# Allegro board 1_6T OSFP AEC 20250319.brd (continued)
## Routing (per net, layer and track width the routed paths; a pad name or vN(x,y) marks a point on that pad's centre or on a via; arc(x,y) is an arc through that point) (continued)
VCC_3V3: length 56
  TOP w0.127: v5(2.22,31.83) C914.1
  TOP w0.14: v2(0.65,37.34) 0.65,37.34 0.77,37.34
  TOP w0.178: U17.11 1.4,37.14 1.2,37.34 0.77,37.34 ; 2.23,31.83 1.93,32.14 U46.12 2.28,32.36 U46.1
  L9_SIG2 w0.254: 2.9,41.84 v6(2.91,41.84)
  L10_GND w0.203: 18.36,34.23 18.36,34.24 17.52,34.24 16.56,35.19 v6(16.56,35.65) ; 18.36,34.23 18.76,34.63 18.76,37.78 18.87,37.9 v6(18.87,38.61) ; 18.36,34.23 18.36,33.19 v6(18.61,32.94)
  L11_GND w0.254: v6(12.33,14.28) 12.84,13.77 v6(13.2,13.77)
  BOTTOM w0.203: 9.4,39.57 9.4,40.53 9.17,40.76 R32.2 R40.2 8.4,41.27 C45.1 7.57,41.29 U22.A1 ; U10.2 2.55,42.19 v6(2.91,41.84) C424.1 2.66,41.55 2.48,41.37 2.48,39.97 2.29,39.78 R580.1 2.02,39.22 2.02,39.22 ; U48.2 8.92,43.31 C909.1 8.23,43.34 8.23,43.34
  BOTTOM w0.254: 8.44,45.52 8.44,43.96 8.23,43.75 8.23,42.29 8.48,42.04 9.47,42.04 10.45,41.05 10.45,39.53 ; 8.44,45.52 8.81,45.88 15.48,45.88 15.94,45.42 15.94,44.89 16.23,44.6 R622.1 16.69,45.06 16.94,45.31 17.46,45.31 17.7,45.08 R23.2 ; 8.44,45.52 8.43,45.5 6.52,45.5 C420.1 U38.12 6.5,44.57 U38.1 ; R579.1 3.28,39.9 2.6,39.22 1.51,39.22 0.65,38.36 v2(0.65,37.34) ; 16.56,35.88 16.24,35.88 16.24,35.88 13.61,35.88 13.38,36.1 12.52,36.1 11.91,36.71 11.91,37.71 11.69,37.92 ; 16.56,35.88 v6(16.56,35.65) ; 16.56,35.88 16.56,36.05 R13.1 ; U24.4 7.31,38.81 7.31,38.82 ; R29.1 8.16,38.91 8.16,38.91
  vias: v2(9.58,14.77) v2(9.57,14.44) v2(9.56,14.03) v2(9.94,14.79) v2(9.94,14.41) v2(9.94,14.03) v2(10.32,14.79) v2(10.32,14.41) v2(10.32,14.03) v2(10.7,14.79) v2(10.7,14.41) v2(10.7,14.03) v2(11,14.65) v2(11.04,14.31) v6(1.38,34.87) v6(1.38,34.58) v6(1.38,34.28) v6(1.4,26.29) v6(1.4,25.86) v6(1.41,24.97) v6(1.41,24.51) v6(1.67,34.88) v6(1.66,34.59) v6(1.66,34.29) v6(1.77,26.29) v6(1.77,25.86) v6(1.77,24.97) v6(1.77,24.51) v7(0.64,17.04) v7(0.64,16.68) v7(0.64,16.33) v7(0.64,15.97) v7(0.64,15.62) v7(1,17.04) v7(1,16.68) v7(1,16.33) v7(1,15.97) v7(1,15.62) v7(1.38,34.87) v7(1.38,34.58) v7(1.38,34.28) v7(1.4,26.29) v7(1.4,25.86) v7(1.41,24.97) v7(1.41,24.51) v7(1.67,34.88) v7(1.66,34.59) v7(1.66,34.29) v7(1.77,26.29) v7(1.77,25.86) v7(1.77,24.97) v7(1.77,24.51) v8(1.38,34.87) v8(1.38,34.58) v8(1.38,34.28) v8(1.4,26.29) v8(1.4,25.86) v8(1.41,24.97) v8(1.41,24.51) v8(1.67,34.88) v8(1.66,34.59) v8(1.66,34.29) v8(1.77,26.29) v8(1.77,25.86) v8(1.77,24.97) v8(1.77,24.51) v10(0.64,17.04) v10(0.64,16.68) v10(0.64,16.33) v10(0.64,15.97) v10(0.64,15.62) v10(1,17.04) v10(1,16.68) v10(1,16.33) v10(1,15.97) v10(1,15.62) v11(0.64,17.04) v11(0.64,16.68) v11(0.64,16.33) v11(0.64,15.97) v11(0.64,15.62) v11(1,17.04) v11(1,16.68) v11(1,16.33) v11(1,15.97) v11(1,15.62)
VCC_3V3_DMM: length 5.3
  L11_GND w0.071: v6(18.2,43.93) 18.52,43.62 18.52,42.44 18.16,42.09 17.5,42.09 16.22,40.81 v6(16.22,40.8)
  BOTTOM w0.14: R23.1 R24.1 18.2,43.93 v6(18.2,43.93)
VCC_OSFP: length 43.2
  L7_PWR2 w0.076: v7(19.89,43.66) 19.89,43.12 18.52,41.75 18.52,40.41 18.02,39.91 18.02,38.77 17.67,38.42 17.67,37.87 17.98,37.56 17.98,34 19,32.98 19,29.94 18.01,28.95 18.01,19.32 17.37,18.67 17.37,12.58 16.85,12.07 10.95,12.07 v2(10.94,12.08)
  L10_GND w0.081: v7(19.89,43.66) 19.9,43.66 v6(19.9,43.92)
  BOTTOM w0.14: C939.2 12.5,12.37 12.35,12.22 11.2,12.22 U32.1 ; R600.2 19.76,44.6 19.9,44.46 v6(19.9,43.92)
  vias: v1(10.81,2.92) v1(10.81,2.61) v1(10.81,2.31) v1(10.81,2) v1(10.81,1.7) v1(10.81,1.39) v2(9.58,12.08) v2(9.91,11.62) v2(9.91,11.21) v2(9.91,10.81) v2(9.91,10.4) v2(9.91,9.99) v2(9.92,9.17) v2(9.92,8.16) v2(9.92,7.14) v2(9.92,6) v2(9.92,4.98) v2(9.99,4.3) v2(9.99,3.89) v2(10.04,12.07) v2(10.04,3.46) v2(10.2,2.92) v2(10.2,2.61) v2(10.2,2.31) v2(10.2,2) v2(10.2,1.7) v2(10.2,1.39) v2(10.32,11.62) v2(10.32,11.21) v2(10.32,10.81) v2(10.32,10.4) v2(10.32,9.99) v2(10.27,3.21) v2(10.4,4.3) v2(10.4,3.89) v2(10.4,3.48) v2(10.5,2.92) v2(10.5,2.61) v2(10.5,2.31) v2(10.5,2) v2(10.5,1.7) v2(10.5,1.39) v2(10.55,12.04) v2(10.55,8.79) v2(10.55,7.9) v2(10.55,6.76) v2(10.55,5.62) v2(10.55,4.6) v2(10.72,11.62) v2(10.72,11.21) v2(10.72,10.81) v2(10.72,10.4) v2(10.72,9.99) v2(10.81,4.3) v2(10.81,3.89) v2(10.81,3.48) v6(9.89,2.92) v6(9.89,2.61) v6(9.89,2.31) v6(9.89,2) v6(9.89,1.7) v6(9.89,1.39)
VDD_0P6: length 37
  TOP w0.132: U1.E15 v2(5.91,29.61)
  L2_GND w0.127: v4(1.94,21.01) 1.26,20.32 1.26,15.85 3.75,13.36 5.9,13.36 v1(6.3,12.97) ; v2(6.98,27.61) 6.98,27.11 6.34,26.48 v4(5.35,26.48)
  L3_GND w0.254: v4(17.85,37.75) 17.85,36.65 17.6,36.4 17.6,36.05 17.59,36.04 17.59,33.42 17.94,33.06 17.94,30.38 17.69,30.13 17.33,30.13 16.82,29.61 v2(15.48,29.61)
  L4_SIG1 w0.127: v4(1.94,21.01) 2.15,21.21 2.15,22.13 3.14,23.12 3.14,25.02 3.62,25.51 4.76,25.51 5.35,26.09 v4(5.35,26.48)
  L4_SIG1 w0.203: v9(18.18,40.88) 18.18,39.61 17.72,39.15 17.72,37.88 v4(17.85,37.75)
  L9_SIG2 w0.074: v9(18.18,40.88) 18.18,40.88
  L9_SIG2 w0.203: 18.18,40.88 17.94,40.88 17.74,40.67 17.05,40.67 v6(16.83,40.45)
  vias: v1(2.55,21.59) v1(2.93,21.59) v1(3.31,21.26) v1(3.93,21.14) v1(4.28,20.41) v1(4.28,19.9) v1(4.45,21.15) v1(4.79,20.42) v1(4.79,19.92) v1(4.95,21.15) v1(5.3,20.42) v1(5.3,19.92) v1(5.46,21.15) v1(5.81,20.42) v1(5.81,19.92) v1(5.97,21.15) v1(6.31,20.42) v1(6.31,19.92) v1(6.48,21.15) v1(6.82,20.42) v1(6.82,19.92) v1(7.33,20.42) v1(7.33,19.92) v1(7.84,20.42) v1(7.84,19.92) v1(7.87,19.36) v1(7.87,18.85) v1(8.35,20.42) v1(8.35,19.92) v1(8.37,19.36) v1(8.37,18.85) v1(9.11,20.34) v1(9.66,20.36) v2(2.48,21.26) v2(2.48,20.86) v2(2.48,20.45) v2(2.48,20.04) v2(2.48,19.64) v2(2.88,21.26) v2(2.88,20.86) v2(2.88,20.45) v2(2.88,20.04) v2(2.88,19.64) v2(3.31,20.86) v2(3.29,20.45) v2(3.29,20.04) v2(3.29,19.64) v2(3.69,20.45) v2(3.69,20.04) v2(3.69,19.64) v2(5.48,29.11) v2(6.48,28.11) v2(6.98,28.61) v2(7.48,29.11) v2(7.98,29.61) v2(8.48,28.11) v2(8.98,28.61) v2(8.98,27.61) v2(9.48,29.11) v2(9.98,29.61) v2(10.98,29.11) v2(11.48,29.61) v2(11.98,28.11) v2(12.48,28.61) v2(12.48,27.61) v2(12.98,29.11) v2(13.48,29.61) v2(13.98,28.11) v2(14.48,28.61) v2(14.48,27.61) v2(15.04,29.11) v3(2.55,21.59) v3(2.93,21.59) v3(3.31,21.26) v4(2.55,21.59) v4(2.93,21.59) v4(3.31,21.26) v9(2.55,21.59) v9(2.93,21.59) v9(3.31,21.26)
VDD_0P6_EN: length 44.7
  TOP w0.14: v1(8.74,12.65) R635.1 8.35,12.65 R607.1
  L2_GND w0.071: v3(18.3,10.92) 18.3,11.12 17.4,12.02 14.73,12.02 14.1,12.65 v1(8.74,12.65)
  L3_GND w0.081: v3(18.3,10.92) 17.8,11.42 17.8,14.56 18.65,15.41 18.65,17.93 20.03,19.31 20.03,26.97 19.32,27.67 19.32,35.41 19.11,35.62 19.11,37.23 19.54,37.66 v9(19.54,38.01)
  L9_SIG2 w0.074: v9(19.54,38.01) 19.49,37.97 19.49,37.97 19.42,37.9 17.94,37.9 16.98,38.87 16.98,39.16 arc(16.92,39.36) 16.77,39.51 arc(16.69,39.54) 16.6,39.55 arc(16.52,39.54) 16.45,39.51 16.32,39.46 arc(16.3,39.46) 16.27,39.46 16.18,39.46 arc(16.12,39.46) 16.07,39.49 v6(15.92,39.57)
VDD_0P6_PG: length 7.7
  TOP w0.14: R620.2 3.03,12.12 v1(3.58,12.12) 3.85,12.12 4.27,12.53 U20.21
  L2_GND w0.071: v8(2.63,11.23) 2.63,11.55 3.19,12.12 v1(3.58,12.12)
  L11_GND w0.071: v6(5.77,12.22) 5.54,11.99 5.21,11.99 5.2,11.99 3.13,11.99 2.91,11.76 2.91,11.51 v8(2.63,11.23)
  BOTTOM w0.14: v6(5.77,12.22) U21.21
VDD_0P94: length 22.4
  L2_GND w0.127: v4(18.53,19.66) 18.77,19.42 19.26,19.42 19.71,18.97 19.71,15.87 17.89,14.05 17.87,14.05 16.87,13.05 v1(16.87,12.99)
  L7_PWR2 w0.254: v8(18.75,40.24) 18.96,40.03 18.96,36.8 19.69,36.07 19.69,34.78 19.28,34.37 19.28,29.17 19.57,28.88 19.54,28.86
  L11_GND w0.254: v8(18.75,40.24) 18.45,40.24 17.54,41.15 v6(17.46,41.15)
  BOTTOM w0.203: U2.T10 v6(17.46,41.15)
  vias: v1(12.11,20.39) v1(12.11,19.88) v1(12.62,20.39) v1(12.62,19.88) v1(13.12,20.39) v1(13.12,19.88) v1(13.68,20.37) v1(13.68,19.86) v1(14.19,20.37) v1(14.19,19.86) v1(14.66,20.95) v1(14.7,20.37) v1(14.7,19.86) v1(15.16,20.95) v1(15.21,20.37) v1(15.21,19.86) v1(15.67,20.95) v1(15.72,20.37) v1(15.72,19.86) v1(16.18,20.95) v1(16.22,20.37) v1(16.22,19.86) v1(16.69,20.95) v1(16.73,20.37) v1(16.73,19.86) v1(17.2,20.95) v1(17.24,20.37) v1(17.24,19.86) v1(17.77,21.24) v1(17.77,20.96) v1(17.77,20.68) v1(17.77,20.4) v1(17.77,20.12) v1(18.05,21.24) v1(18.05,20.96) v1(18.05,20.68) v1(18.05,20.4) v1(18.05,20.12) v1(19.09,23.42) v1(19.09,23.14) v1(19.09,22.86) v1(19.39,23.43) v1(19.39,23.15) v1(19.39,22.87) v1(19.66,23.43) v1(19.66,23.15) v1(19.66,22.87) v2(10.45,20.65) v2(10.45,20.3) v2(10.45,19.97) v2(10.81,20.3) v2(10.83,19.97) v3(17.77,21.24) v3(17.77,20.96) v3(17.77,20.68) v3(17.77,20.4) v3(17.77,20.12) v3(18.05,21.24) v3(18.05,20.96) v3(18.05,20.68) v3(18.05,20.4) v3(18.05,20.12) v3(19.09,23.42) v3(19.09,23.14) v3(19.09,22.86) v3(19.39,23.43) v3(19.39,23.15) v3(19.39,22.87) v3(19.66,23.43) v3(19.66,23.15) v3(19.66,22.87) v4(17.77,21.24) v4(17.77,20.96) v4(17.77,20.68) v4(17.77,20.4) v4(17.77,20.12) v4(18.05,21.24) v4(18.05,20.96) v4(18.05,20.68) v4(18.05,20.4) v4(18.05,20.12) v4(19.09,23.42) v4(19.09,23.14) v4(19.09,22.86) v4(19.39,23.43) v4(19.39,23.15) v4(19.39,22.87) v4(19.66,23.43) v4(19.66,23.15) v4(19.66,22.87) v6(18.77,28.84) v6(18.77,28.54) v6(18.77,28.23) v6(19.08,28.85) v6(19.08,28.54) v6(19.08,28.24) v6(19.41,28.85) v6(19.41,28.54) v6(19.41,28.24) v7(18.77,28.84) v7(18.77,28.54) v7(18.77,28.23) v7(19.08,28.85) v7(19.08,28.54) v7(19.08,28.24) v7(19.12,21.28) v7(19.12,20.95) v7(19.12,20.62) v7(19.12,20.29) v7(19.12,19.96) v7(19.41,28.85) v7(19.41,28.54) v7(19.41,28.24) v7(19.37,21.11) v7(19.37,20.78) v7(19.37,20.45) v7(19.37,20.12) v7(19.37,19.79) v8(18.77,28.84) v8(18.77,28.54) v8(18.77,28.23) v8(19.08,28.85) v8(19.08,28.54) v8(19.08,28.24) v8(19.41,28.85) v8(19.41,28.54) v8(19.41,28.24) v9(18.77,28.84) v9(18.77,28.54) v9(18.77,28.23) v9(19.08,28.85) v9(19.08,28.54) v9(19.08,28.24) v9(19.12,21.28) v9(19.12,20.95) v9(19.12,20.62) v9(19.12,20.29) v9(19.12,19.96) v9(19.41,28.85) v9(19.41,28.54) v9(19.41,28.24) v9(19.37,21.11) v9(19.37,20.78) v9(19.37,20.45) v9(19.37,20.12) v9(19.37,19.79)
VDD_0P94_EN: length 34.5
  TOP w0.14: R715.1 v3(18.12,12.13) 18.01,12.13 R710.1
  L3_GND w0.081: v8(19.41,37.01) 19.41,35.75 19.58,35.57 19.58,27.75 20.25,27.08 20.25,19.12 18.89,17.76 18.89,15.36 17.99,14.46 17.99,12.26 v3(18.12,12.13)
  L11_GND w0.071: v8(19.41,37.01) 18.38,37.01 17.77,37.62 16.42,37.62 16.3,37.5 14.36,37.5 v6(13.8,38.05)
  BOTTOM w0.14: v6(13.8,38.05) 13.8,38.5 13.8,38.51 13.81,38.52 14.51,39.22 U2.E1
VDD_0P94_PG: length 2.3
  TOP w0.14: U26.21 14.68,12.44 14.53,12.29 13.1,12.29 R621.2
VDD_1P2: length 28.3
  L10_GND w0.081: v6(16.52,39.92) 16.77,40.06 17.33,40.06 17.54,39.86 18.67,39.86 19.19,39.34 19.19,38.64 20.23,37.6 20.23,17.98 v6(19.65,17.4)
  BOTTOM w0.14: 13.47,17.42 U37.A3
  BOTTOM w0.178: 18.12,17.76 19.29,17.76 v6(19.65,17.4)
VDD_1P2_EN: length 42.5
  L9_SIG2 w0.074: v6(19.22,10.97) 19.22,11.8 17.91,13.1 17.91,16.73 20.17,18.99 20.17,29.35 19.24,30.28 19.24,34.46 19.72,34.93 19.72,37.25 19.45,37.52 v8(19.24,37.52)
  L11_GND w0.071: v6(14.18,38.08) 14.18,38.03 14.54,37.67 16.16,37.67 16.29,37.8 18.45,37.8 18.73,37.52 v8(19.24,37.52)
  BOTTOM w0.14: v6(14.18,38.08) 14.18,38.51 14.55,38.87 U2.C1 ; v6(19.22,10.97) 19.22,11.68 18.01,12.89 R850.1 14.47,12.89 14.17,13.2 R852.1
VDD_1P2_PG: length 0.6
  BOTTOM w0.14: U37.A2 13.85,16.45 R756.1
VDD_1P8: length 87.9
  TOP w0.127: 1.41,32 v1(1.42,32.01) ; C915.1 1.41,32
  TOP w0.178: 1.41,32 U46.11
  TOP w0.203: R22.1 18.99,33.33 19.35,32.97 19.35,30.65 19.35,30.64 19.35,30.15 19.02,29.82 R693.2 19.38,29.4 v1(19.38,29.29) ; U1.AD12 v2(15.48,28.36) U1.AD13 ; R854.2 19.37,29.27 v1(19.38,29.29) ; v2(5.48,28.61) v2(5.48,28.11) ; v1(19.38,29.29) 19.88,29.29 v3(19.93,29.34) ; v1(19.38,29.29) v1(18.3,29.29) ; R769.1 R819.1 R818.1 R694.2 1.74,26.8 R691.2 0.89,26.8 0.69,26.6 R75.2 ; C426.1 1.29,35.44 v1(1.39,35.54) 1.4,35.55 U17.1
  TOP w0.254: v1(18.98,25.99) 18.98,25.98 R690.2 ; R694.2 1.77,26.6 1.97,26.4 2.57,26.4 2.7,26.53 v9(2.7,26.53)
  L2_GND w0.203: v2(15.48,28.36) 16.4,29.29 v1(18.3,29.29) ; v1(1.42,32.01) 2.09,32.68 2.09,33.9 1.83,34.15 1.83,34.74 1.73,34.85 1.73,35.2 v1(1.39,35.54) 2.41,35.54 2.5,35.44 v9(2.84,35.44) 2.82,35.42 v1(2.82,34.77) ; v1(19.38,29.29) 19.38,26.39 v1(18.98,25.99)
  L3_GND w0.254: v9(19.93,33.47) v3(19.93,29.34)
  L4_SIG1 w0.203: v4(2.11,23.14) 1.97,23.28 1.97,24.6 v2(5.48,28.11)
  L6_PWR1 w0.254: v9(18.81,42.94) 18.54,42.67 17.71,42.67 17.52,42.86 v9(3.67,42.86)
  L9_SIG2 w0.254: v9(18.81,42.94) v6(18.81,42.44) 18.81,42.18 20.06,40.93 20.06,33.6 v9(19.93,33.47) ; v9(2.7,26.53) 3.21,27.04 3.21,28.85
  L11_GND w0.203: v6(11,43.4) 11,43.77 10.4,44.38 8.01,44.38 7.45,43.81 7.09,43.81 6.67,44.22 5.71,44.22 5.11,43.63 v6(4.08,43.63) 3.84,43.63 v8(3.67,43.46)
  L11_GND w0.254: v6(6.63,35.13) 3.21,35.13 2.92,35.42 2.92,35.9 v6(2.66,36.17)
  BOTTOM w0.203: C83.2 2.66,36.87 v6(2.66,36.17) U8.A2 ; R583.1 R855.1 R856.1 ; R856.1 4.08,44.32 4.61,44.85 C421.1 5,45.04 U38.11 ; R856.1 3.4,44.17 3.11,43.88 C425.2 2.55,43.67 U10.6 ; C932.2 6.33,35.13 v6(6.63,35.13) U47.A2 ; U48.6 10.91,43.31 v6(11,43.4)
  BOTTOM w0.254: R841.2 18.79,42.46 v6(18.81,42.44)
VDD_3P3: length 1
  TOP w0.254: U1.D5 v2(5.48,24.86) U1.D6 ; U1.AD5 v2(15.48,24.66) U1.AD6
  vias: v6(2.88,24.84) v6(2.88,24.56) v6(3.17,24.84) v6(3.17,24.56) v7(2.88,24.84) v7(2.88,24.56) v7(3.17,24.84) v7(3.17,24.56) v8(2.88,24.84) v8(2.88,24.56) v8(3.17,24.84) v8(3.17,24.56)
VDD_3P3_ESD0:
  vias: v2(5.48,25.61)
VDD_3P3_ESD1:
  vias: v2(15.48,25.61)
VDDEFUSE_0P94: length 1.2
  L9_SIG2 w0.254: v7(10.7,28.71) 10.48,28.48 v2(10.48,27.61)
  BOTTOM w0.14: C940.1 arc(10.45,30.11) v2(10.48,30.11)
  vias: v6(17.35,22.99) v8(17.35,22.99)
VDDIO_1P8_EN: length 18.7
  L11_GND w0.071: v6(1.71,37.04) 1.84,37.16 2.25,37.16 2.37,37.04 2.88,37.04 3.47,37.63 4.72,37.63 6.04,38.94 13.96,38.94 14.89,38.02 15.95,38.02 16.22,38.29 v6(16.22,39.05)
  BOTTOM w0.14: v6(1.71,37.04) 1.71,35.85 R602.1 1.72,35.62 1.92,35.41 U8.B1
VIN1: length 5.2
  TOP w0.178: R629.1 R618.1 7.75,14.73 v1(7.76,14.74)
  TOP w0.203: 2.55,13.99 2.55,15.04 ; 2.55,13.99 2.41,13.84 R620.1 ; 2.55,13.99 2.57,14 U20.18
  vias: v1(1.92,16.09) v1(1.92,15.79) v1(2.22,16.09) v1(2.22,15.79) v1(2.22,15.48) v1(2.53,16.09) v1(2.53,15.79) v1(2.53,15.48) v1(2.83,16.09) v1(2.83,15.79) v1(2.83,15.48) v1(3.17,15.45) v1(7.07,15.4) v1(7.07,15.07) v1(7.05,14.74) v1(7.4,15.4) v1(7.4,15.07) v1(7.4,14.74) v1(7.76,15.4) v1(7.76,15.07) v1(8.14,15.4) v1(8.14,15.07) v1(8.14,14.74)
VIN2: length 2.7
  TOP w0.14: 12.9,14.57 R621.1 ; U26.18 13.5,14 13.3,14.2 13.3,14.48
  vias: v1(12.39,15.4) v1(12.39,15.09) v1(12.39,14.79) v1(12.7,15.4) v1(12.7,15.09) v1(12.7,14.79) v1(13,15.4) v1(13,15.09) v1(13,14.79) v1(13.31,15.4) v1(13.31,15.09) v1(13.31,14.79) v1(17.63,15.72) v1(17.64,15.43) v1(17.63,15.14) v1(17.95,16.03) v1(17.94,15.74) v1(17.94,15.44) v1(17.94,15.14) v1(18.27,16.03) v1(18.27,15.73) v1(18.28,15.44) v1(18.57,16.02) v1(18.57,15.72)
VIN3: length 2.8
  L11_GND w0.203: v6(14.17,15.37) v6(13.82,15.37) v6(13.47,15.37) 12.89,15.37 v6(12.89,15.37)
  BOTTOM w0.196: v6(13.47,15.37) v6(13.82,15.37)
  BOTTOM w0.203: v6(14.17,15.37) v6(13.82,15.37) ; C648.1 12.7,15.37 v6(13.47,15.37)
VIN4: length 3.4
  L11_GND w0.203: v6(2.34,14.91) 2.46,14.78 2.46,12.71 v6(1.65,11.9)
  vias: v6(1.96,15.72) v6(1.96,15.44) v6(1.96,15.16) v6(2.24,15.72) v6(2.24,15.44) v6(2.24,15.16) v6(2.52,15.72) v6(2.52,15.44) v6(2.52,15.16) v6(2.8,15.72) v6(2.8,15.44) v6(2.8,15.16) v6(7.08,15.85) v6(7.08,15.46) v6(7.08,15.08) v6(7.33,15.65) v6(7.33,15.27) v6(7.33,14.89) v6(7.68,15.65) v6(7.68,15.27) v6(7.68,14.89) v6(8.01,15.65) v6(8.01,15.27) v6(8.04,14.89)
BOOT0: length 3.5
  L10_GND w0.081: v6(16.83,39.05) 16.83,38.78 16.69,38.64 16.69,37.86 17.03,37.52 17.03,36.92 v6(16.79,36.67)
  BOTTOM w0.14: v6(16.79,36.67) 16.74,36.63 R13.2 16.45,36.63 16.21,36.38 R63.2
CABLE_END_DETECT: length 5.2
  L9_SIG2 w0.074: v6(17.18,43.56) 17.18,43.49 16.39,42.7 16.39,40.68 15.92,40.2 v6(15.92,39.92)
  BOTTOM w0.14: R622.2 R623.2 17.19,43.57 v6(17.18,43.56)
COMP1: length 2.4
  TOP w0.14: R608.1 C81.1 5.32,12.12 5.27,12.18 U20.23
  L2_GND w0.071: v1(5.27,12.04) 5.04,12.27 v6(4.74,12.27)
  BOTTOM w0.14: U21.23 4.77,12.3 v6(4.74,12.27)
DEBUG_I2C_EN: length 9.9
  L10_GND w0.081: v8(15.65,42.03) 15.47,41.85 15.47,41.55 15.02,41.1 15.02,40.15 15.25,39.92 v6(15.31,39.92)
  L11_GND w0.071: v6(11.19,42.93) 14.03,42.93 14.71,42.24 15.43,42.24 v8(15.65,42.03)
  BOTTOM w0.102: 9.87,42.33 U48.8
  BOTTOM w0.14: 9.87,42.33 10.02,42.17 R840.1 10.95,42.48 10.95,42.69 v6(11.19,42.93)
DSP_CLK_EN: length 32.7
  L8_GND w0.076: v8(18.21,42.57) 18.55,42.23 18.55,40.8 17.97,40.23 17.97,38.86 17.33,38.21 17.33,37.3 16.18,36.15 v8(16.18,35.72)
  L10_GND w0.081: v8(3.63,33.97) 3.38,33.71 3.38,31.82 4.35,30.85 v6(4.35,28.51)
  L11_GND w0.071: v6(16.56,41.56) 16.58,41.53 16.69,41.53 17.45,42.29 17.93,42.29 v8(18.21,42.57) ; v8(3.63,33.97) 3.63,33.97 10.37,33.97 v6(10.47,34.07) 10.47,35.13 11.3,35.95 15.95,35.95 v8(16.18,35.72)
  BOTTOM w0.14: v6(16.56,41.56) 16.52,41.53 U2.R7 ; v6(4.35,28.51) 4.35,28.51 Y1.1 ; Y2.1 10.98,33.41 10.47,33.92 v6(10.47,34.07)
DSP_I2C_SCL_18: length 30.7
  TOP w0.14: U1.A12 3.69,28.11 2.96,27.38 v3(2.29,27.38)
  L3_GND w0.081: v3(2.29,27.38) 2.68,27.77 2.68,30.05 3.26,30.63 3.26,34.05 3.27,34.07 3.27,34.08 3.94,34.74 3.94,36.81 3.88,36.87 3.88,38.02 3.98,38.12 v4(3.98,38.41)
  L4_SIG1 w0.074: v4(3.98,38.41) 3.98,38.83 3.63,39.17 3.15,39.17 1.29,41.04 1.29,43.04 1.9,43.65 v9(2.67,43.65)
  L9_SIG2 w0.074: v9(2.67,43.65) 2.89,43.43 v6(2.89,43.17)
  L11_GND w0.071: v6(2.89,43.17) 3.17,43.17 3.33,43.01 4.05,43.01 4.13,43.09 5.25,43.09 5.87,43.71 6.53,43.71 6.91,43.34 7.3,43.34 7.71,42.93 8.01,42.93 8.53,42.41 10,42.41 v6(10.26,42.67)
  BOTTOM w0.14: v6(10.26,42.67) 10.26,42.67 U48.7 ; U10.7 2.95,43.12 v6(2.89,43.17)
DSP_I2C_SDA_18: length 59.1
  TOP w0.14: v1(17.65,26.61) 17.65,26.61 U1.AG9
  L2_GND w0.071: v1(4.48,28.61) 3.98,28.12 2.48,28.12 v4(2.29,27.92) ; v4(1.75,22.84) 2.49,22.1 3.33,22.1 3.73,21.71 16.57,21.71 17.53,22.67 17.53,24.13 18.32,24.92 18.32,25.66 18.55,25.89 18.55,26.31 18.16,26.7 17.74,26.7 v1(17.65,26.61)
  L3_GND w0.081: v4(3.61,38.8) 3.62,38.8 3.7,38.72 3.7,36.8 3.76,36.74 3.76,34.88 3.07,34.19 3.07,30.77 2.48,30.17 2.48,28.3 2.49,28.29 2.49,28.12 v4(2.29,27.92)
  L4_SIG1 w0.074: v9(1.03,43.22) 0.61,42.8 0.61,40.88 0.9,40.58 1.48,40.58 3.27,38.8 v4(3.61,38.8) ; v4(1.75,22.84) 1.54,23.06 1.54,27.17 v4(2.29,27.92)
  L9_SIG2 w0.074: v6(1.66,43.24) 1.05,43.24 v9(1.03,43.22)
  L11_GND w0.071: v6(10.26,43.98) 10.14,44.1 8.21,44.1 7.69,43.57 6.92,43.57 6.61,43.88 5.77,43.88 5.15,43.26 4.05,43.26 3.97,43.18 3.52,43.18 3.23,43.48 1.89,43.48 v6(1.66,43.24)
  BOTTOM w0.14: U10.5 1.78,43.12 v6(1.66,43.24) ; U48.5 10.26,43.98 v6(10.26,43.98)
DSP_PGOOD_M: length 12
  L10_GND w0.081: v8(16.66,43.3) 16.66,42.28 16.26,41.88 16.26,41.43 15.91,41.08 15.91,40.85 15.61,40.55 v6(15.61,40.1)
  L11_GND w0.071: v8(16.66,43.3) 16.66,43.49 16.31,43.84 12.74,43.84 11.1,45.48 v6(9.59,45.48)
  BOTTOM w0.14: R105.2 9.59,45.43 v6(9.59,45.48)
DSP_REFCLK0_N: length 2.9
  BOTTOM w0.127: v2(3.98,32.11) 3.98,32.08 3.71,31.81 3.36,31.81 3.2,31.97 3.2,32.8 3.08,32.92 2.68,32.92 2.59,32.83 2.59,32.66 2.7,32.54 C50.2
DSP_REFCLK0_P: length 2.9
  BOTTOM w0.127: v2(3.98,32.61) 3.91,32.55 3.67,32.55 3.59,32.64 3.59,32.96 3.24,33.31 2.52,33.31 2.21,32.99 2.21,32.64 C51.2
DSP_REFCLK1_N: length 3.2
  BOTTOM w0.127: v2(16.98,32.11) 16.74,32.21 16.67,32.25 16.01,32.91 16.01,34.24 15.83,34.42 15.66,34.42 C651.2
DSP_REFCLK1_P: length 3.2
  BOTTOM w0.127: v2(16.98,32.61) 16.87,32.61 16.39,33.09 16.39,34.42 16.01,34.8 15.7,34.8 C650.2
EEPROM_MISO: length 25.1
  TOP w0.14: v4(2.88,35.88) 2.88,35.89 U17.5 2.78,35.32 R30.1 ; v3(17.01,28.08) U1.AG12
  L3_GND w0.081: v4(17.99,36.21) 17.99,35.52 17.86,35.38 17.86,33.53 18.22,33.17 18.22,29.28 v3(17.01,28.08)
  L4_SIG1 w0.074: v4(2.88,35.88) 2.88,36.03 3.2,36.35 17.86,36.35 v4(17.99,36.21)
EEPROM_MOSI: length 8
  TOP w0.14: v4(2.11,35.13) 2.09,35.14 U17.3
  L4_SIG1 w0.074: v4(4.98,29.61) 4.56,29.61 3.69,30.49 3.69,30.64 2.91,31.42 2.91,32.86 1.82,33.95 1.82,34.83 v4(2.11,35.13)
EEPROM_SCK: length 6.7
  TOP w0.14: v4(2.35,34.39) 2.2,34.39 1.71,34.87 1.71,36.17 U17.2
  L4_SIG1 w0.074: v4(4.48,31.11) 3.78,31.11 3.26,31.63 3.26,33.16 2.35,34.08 v4(2.35,34.39)
EEPROM_SS_N: length 7.4
  TOP w0.14: v4(2.36,34.8) 2.43,34.87 2.43,36.15 U17.4
  L4_SIG1 w0.074: v4(2.36,34.8) 2.19,34.8 2,34.61 2,34.1 3.09,33.02 3.09,31.58 4.48,30.19 v4(4.48,30.11)
EEPROM_WP_N: length 28
  L11_GND w0.071: v6(16.83,40.1) 16.92,40.01 18.04,40.01 18.61,39.44 19.63,39.44 19.86,39.2 19.86,37.07 19.53,36.73 19.3,36.73 19.19,36.84 18.3,36.84 18.1,37.04 17.15,37.04 16.78,37.41 16.46,37.41 16.37,37.33 14.29,37.33 13.99,37.62 13.58,37.62 12.64,38.56 6.15,38.56 4.67,37.08 v6(3.68,37.08)
  BOTTOM w0.14: U22.C2 6.11,40.18 5.76,39.84 5.35,39.84 3.68,38.17 R857.1 v6(3.68,37.08)
EN1: length 6.2
  TOP w0.14: v1(7.24,12.65) 7.1,12.65 6.96,12.79 6.96,13.26 6.71,13.5 U20.2
  L2_GND w0.071: v2(2.84,12.44) 2.98,12.58 5.11,12.58 5.52,12.17 6.76,12.17 v1(7.24,12.65)
HRXN1: length 13.4
  L4_SIG1 w0.071: v4(15.48,22.61) 15.48,22.61 15.59,22.5 15.59,21.83 arc(15.68,21.24) 15.92,20.7 arc(16.06,20.46) 16.18,20.2 arc(16.38,19.64) 16.48,19.06 arc(16.48,19.03) 16.48,18.99 16.48,18.72 16.48,9.84 arc(16.44,9.62) v4(16.31,9.43)
HRXN2: length 14.4
  L9_SIG2 w0.071: v9(15.48,23.61) 15.59,23.49 15.59,20.33 arc(15.6,20.16) 15.6,19.99 arc(15.71,18.95) 16.04,17.95 arc(16.33,17.16) 16.48,16.32 arc(16.48,16.29) 16.48,16.26 16.48,9.84 arc(16.44,9.62) v6(16.31,9.43)
HRXN3: length 11.9
  L4_SIG1 w0.071: v4(13.98,22.61) 14.09,22.5 14.09,21.83 arc(14.17,21.3) 14.42,20.82 arc(14.49,20.7) 14.57,20.58 arc(14.86,19.88) 14.96,19.13 14.96,11.37 arc(14.91,11.15) v4(14.79,10.96)
HRXN4: length 12.8
  L9_SIG2 w0.071: v9(13.98,23.61) 14.09,23.49 14.09,22.11 arc(14.11,21.56) 14.15,21.01 arc(14.16,20.99) 14.16,20.98 arc(14.35,19.82) 14.61,18.68 arc(14.87,17.38) 14.96,16.06 14.96,11.37 arc(14.91,11.15) v6(14.79,10.96)
HRXN5: length 13.4
  L4_SIG1 w0.071: v4(12.48,22.61) 12.48,22.61 12.59,22.5 12.59,21.84 arc(12.64,21.41) 12.78,21.01 13.12,20.33 arc(13.35,19.68) 13.43,19 13.43,9.84 arc(13.39,9.62) v4(13.26,9.43)
HRXN6: length 14.4
  L9_SIG2 w0.071: v9(12.48,23.61) 12.59,23.49 12.59,22.41 arc(12.69,21.39) 12.97,20.4 arc(13.31,19.2) 13.43,17.96 13.43,9.84 arc(13.39,9.62) v6(13.26,9.43)
HRXN7: length 11.7
  L4_SIG1 w0.071: v4(10.98,22.61) 11.09,22.5 11.09,21.83 arc(11.2,21.16) 11.53,20.55 arc(11.75,20.21) 11.87,19.83 arc(11.87,19.78) 11.88,19.73 arc(11.9,19.27) 11.91,18.81 11.91,11.62 arc(11.86,11.4) v4(11.74,11.21)
HRXN8: length 12.6
  L9_SIG2 w0.071: v6(11.74,11.21) 11.79,11.26 arc(11.88,11.39) 11.91,11.55 arc(11.91,11.56) 11.91,11.58 11.91,18.75 arc(11.9,19.04) 11.88,19.34 arc(11.77,19.98) 11.51,20.59 arc(11.2,21.35) 11.09,22.17 11.09,23.49 v9(10.98,23.61)
HRXP1: length 13.4
  L4_SIG1 w0.071: v4(15.98,22.61) 15.86,22.5 15.86,21.83 arc(15.94,21.32) 16.15,20.85 arc(16.3,20.58) 16.43,20.31 arc(16.64,19.71) 16.74,19.09 arc(16.75,19.04) 16.75,18.99 16.75,18.99 16.75,18.99 16.75,9.84 arc(16.79,9.62) v4(16.92,9.43)
HRXP2: length 14.4
  L9_SIG2 w0.071: v9(15.98,23.61) 15.86,23.5 15.86,20.34 arc(15.87,20.17) 15.87,19.99 arc(15.98,19.01) 16.29,18.06 arc(16.59,17.23) 16.74,16.35 arc(16.75,16.3) 16.75,16.26 16.75,9.84 arc(16.79,9.62) v6(16.92,9.43)
HRXP3: length 11.9
  L4_SIG1 w0.071: v4(14.48,22.61) 14.36,22.5 14.36,21.83 arc(14.36,21.81) 14.36,21.79 arc(14.39,21.56) 14.45,21.33 arc(14.53,21.15) 14.63,20.97 arc(14.72,20.85) 14.8,20.72 arc(15.12,19.95) 15.23,19.13 15.23,11.37 arc(15.27,11.14) v4(15.39,10.96)
HRXP4: length 12.8
  L9_SIG2 w0.071: v9(14.48,23.61) 14.36,23.5 14.36,22.11 arc(14.38,21.57) 14.42,21.04 arc(14.42,21.02) 14.42,21.01 arc(14.61,19.87) 14.87,18.75 arc(15.14,17.41) 15.22,16.06 15.22,11.37 arc(15.27,11.15) v6(15.39,10.96)
HRXP5: length 13.4
  L4_SIG1 w0.071: v4(12.98,22.61) 12.86,22.5 12.86,21.83 arc(12.9,21.47) 13.02,21.13 13.36,20.45 arc(13.61,19.74) 13.7,19 13.7,9.84 arc(13.75,9.62) v4(13.87,9.43)
HRXP6: length 14.4
  L9_SIG2 w0.071: v9(12.98,23.61) 12.86,23.5 12.86,22.41 arc(12.95,21.44) 13.22,20.5 arc(13.57,19.25) 13.7,17.96 13.7,9.84 arc(13.74,9.62) v6(13.87,9.43)
HRXP7: length 11.7
  L4_SIG1 w0.071: v4(11.48,22.61) 11.36,22.5 11.36,21.83 arc(11.46,21.24) 11.74,20.72 arc(11.99,20.31) 12.14,19.86 12.14,19.85 arc(12.17,19.33) 12.18,18.82 arc(12.18,18.82) 12.18,18.81 12.18,11.62 arc(12.22,11.4) v4(12.35,11.21)
HRXP8: length 12.6
  L9_SIG2 w0.071: v9(11.48,23.61) 11.36,23.5 11.36,22.17 arc(11.46,21.42) 11.74,20.72 arc(12.03,20.06) 12.15,19.35 arc(12.17,19.05) 12.18,18.75 12.18,11.58 arc(12.21,11.4) 12.32,11.24 v6(12.35,11.21)
HTXN1: length 12.6
  L9_SIG2 w0.071: v9(4.98,23.61) 4.86,23.5 4.86,21.93 arc(4.76,19.88) 4.43,17.85 4.43,17.83 arc(4.18,16.26) 4.09,14.66 4.09,11.59 arc(4.13,11.4) 4.24,11.24 4.26,11.21
  vias: v6(4.26,11.21) v7(4.26,11.21) v8(4.26,11.21)
HTXN2: length 11.6
  L4_SIG1 w0.071: v4(4.98,22.61) 4.86,22.5 4.86,21.83 arc(4.75,19.82) 4.43,17.83 arc(4.21,16.53) 4.09,15.21 4.09,11.62 arc(4.14,11.4) v4(4.26,11.21)
HTXN3: length 14.3
  L9_SIG2 w0.071: v9(6.48,23.61) 6.36,23.5 6.36,21.99 arc(6.32,21.16) 6.18,20.34 6.17,20.31 arc(5.76,18.1) 5.62,15.86 5.62,9.84 arc(5.66,9.62) v6(5.79,9.43)
HTXN4: length 13.3
  L4_SIG1 w0.071: v4(6.48,22.61) 6.36,22.5 6.36,21.73 arc(6.28,20.88) 6.11,20.04 arc(5.74,18.09) 5.62,16.1 5.62,9.84 arc(5.66,9.62) v4(5.79,9.43)
HTXN5: length 12.6
  L9_SIG2 w0.071: 7.31,11.21 7.29,11.24 arc(7.18,11.4) 7.14,11.59 7.14,18.5 arc(7.23,19.41) 7.49,20.28 7.58,20.49 arc(7.79,21.22) 7.86,21.98 7.86,23.5 v9(7.98,23.61)
  vias: v6(7.31,11.21) v7(7.31,11.21) v8(7.31,11.21)
HTXN6: length 11.6
  L4_SIG1 w0.071: v4(7.98,22.61) 7.86,22.5 7.86,21.83 arc(7.77,21.11) 7.55,20.42 arc(7.4,20.02) 7.28,19.62 arc(7.2,19.21) 7.15,18.79 arc(7.14,18.73) 7.14,18.67 7.14,18.68 7.14,11.62 arc(7.18,11.4) v4(7.31,11.21)
HTXN7: length 14.4
  L9_SIG2 w0.071: v9(9.48,23.61) 9.36,23.5 9.36,22.04 arc(9.25,21.12) 8.95,20.24 arc(8.74,19.61) 8.66,18.95 8.66,9.84 arc(8.71,9.62) v6(8.83,9.43)
HTXN8: length 13.4
  L4_SIG1 w0.071: v4(9.48,22.61) 9.36,22.5 9.36,21.83 arc(9.28,21.14) 9.05,20.47 9.05,20.45 arc(8.79,19.85) 8.67,19.2 arc(8.66,19.17) 8.66,19.15 8.66,11.96 8.66,9.84 arc(8.71,9.62) v4(8.83,9.43)
HTXP1: length 12.6
  L9_SIG2 w0.071: v9(4.48,23.61) 4.59,23.49 4.59,21.93 arc(4.49,19.9) 4.17,17.89 arc(4.17,17.89) 4.17,17.88 arc(3.91,16.28) 3.82,14.66 3.82,11.55 arc(3.79,11.39) 3.71,11.26 v6(3.65,11.21)
HTXP2: length 11.6
  L4_SIG1 w0.071: v4(4.48,22.61) 4.59,22.5 4.59,21.83 arc(4.49,19.85) 4.17,17.89 arc(3.94,16.56) 3.82,15.22 3.82,11.62 arc(3.78,11.4) v4(3.65,11.21)
HTXP3: length 14.3
  L9_SIG2 w0.071: v9(5.98,23.61) 6.09,23.49 6.09,21.99 arc(6.05,21.19) 5.92,20.4 5.91,20.37 arc(5.49,18.14) 5.35,15.86 5.35,11.58 arc(5.35,11.58) 5.35,11.58 5.35,9.84 arc(5.3,9.62) v6(5.18,9.43)
HTXP4: length 13.3
  L4_SIG1 w0.071: v4(5.98,22.61) 5.98,22.61 6.09,22.5 6.09,21.75 arc(6.01,20.92) 5.85,20.11 arc(5.47,18.12) 5.35,16.1 5.35,9.84 arc(5.3,9.62) v4(5.18,9.43)
HTXP5: length 12.6
  L9_SIG2 w0.071: v9(7.48,23.61) 7.59,23.49 7.59,21.98 arc(7.53,21.27) 7.33,20.59 7.24,20.38 arc(6.97,19.46) 6.87,18.5 6.87,11.55 arc(6.84,11.39) 6.75,11.26 v6(6.7,11.21)
HTXP6: length 11.6
  L4_SIG1 w0.071: v4(7.48,22.61) 7.59,22.5 7.59,21.83 arc(7.51,21.16) 7.3,20.52 arc(7.02,19.69) 6.88,18.81 arc(6.87,18.74) 6.87,18.67 6.87,11.62 arc(6.83,11.4) v4(6.7,11.21)
HTXP7: length 14.4
  L9_SIG2 w0.071: v9(8.98,23.61) 9.09,23.49 9.09,22.05 arc(8.99,21.18) 8.71,20.35 arc(8.48,19.67) 8.4,18.95 8.4,9.84 arc(8.35,9.62) v6(8.23,9.43)
HTXP8: length 13.4
  L4_SIG1 w0.071: v4(8.98,22.61) 9.09,22.5 9.09,21.83 arc(9.02,21.2) 8.81,20.59 arc(8.53,19.93) 8.4,19.22 arc(8.4,19.19) 8.39,19.15 8.39,11.7 8.4,9.84 arc(8.35,9.62) v4(8.23,9.43)
INT/RSTN: length 48.4
  TOP w0.14: J1.44 9.6,3.12 9.46,3.26 9.46,4.43 v4(9.56,4.54)
  L2_GND w0.071: v4(1.54,22.13) 1.41,22.13 1.18,22.36 1.18,24.03 1.61,24.46 1.61,28.14 2.14,28.67 2.14,30.18 3.12,31.16 3.12,34.42 3.23,34.53 v4(3.23,35.38)
  L4_SIG1 w0.074: v8(3.51,35.62) 3.47,35.62 v4(3.23,35.38) ; v4(9.56,4.54) 9.38,4.72 6.44,4.72 4.08,7.08 4.08,8.54 2.31,10.31 2.31,12.49 2.63,12.81 2.63,15.4 1.34,16.69 1.34,19.89 1.54,20.09 v4(1.54,22.13)
  L11_GND w0.071: v6(8.08,36.8) 5.95,36.8 5.59,37.16 5.45,37.16 5.01,36.73 4.66,36.73 3.93,36 3.93,35.87 3.69,35.62 v8(3.51,35.62)
  BOTTOM w0.14: U4.3 9.32,38.33 R657.2 8.63,37.85 8.74,37.74 R3.2 R31.1 v6(8.08,36.8)
LOL_1N: length 21.6
  L3_GND w0.081: v3(4.98,30.11) 3.64,31.45 3.64,33.91 4.34,34.61 v4(4.34,37.61)
  L4_SIG1 w0.074: v8(4.92,39.66) 4.6,39.34 4.6,37.86 v4(4.34,37.61)
  L11_GND w0.071: v6(15.01,40.1) 12.8,40.1 11.95,40.95 9.49,40.95 8.39,39.84 5.66,39.84 5.48,39.66 v8(4.92,39.66)
LOL_2N: length 16.7
  TOP w0.14: U1.AG8 v3(17.28,26.04)
  L3_GND w0.081: v8(18.5,38.67) 18.7,38.67 18.88,38.49 18.88,38.01 18.5,37.64 18.5,35.48 18.22,35.2 18.22,33.68 18.59,33.32 18.59,28.99 17.28,27.68 v3(17.28,26.04)
  L11_GND w0.071: v8(18.5,38.67) 18.19,38.67 17.92,38.94 17.92,39.49 17.57,39.83 16.9,39.83 16.83,39.76 v6(16.83,39.75)
LOL_3N: length 11.6
  L2_GND w0.071: v1(16.48,30.61) 17.38,31.51 17.38,33.5 v9(18.69,34.81)
  L9_SIG2 w0.074: v9(18.69,34.81) 18.69,36.24 17.97,36.96 17.97,37.44 16.93,38.48 16.5,38.48 15.61,39.37 v6(15.61,39.75)
LOL_4N: length 13.7
  L3_GND w0.081: v4(17.43,36.85) 17.32,36.74 17.32,33.31 17.64,32.99 17.64,31.71 17.01,31.09 v3(17.01,30.65)
  L4_SIG1 w0.074: v9(17.47,41.03) 17.47,41.01 17.89,40.59 17.89,39.71 17.35,39.17 17.35,36.93 v4(17.43,36.85)
  L9_SIG2 w0.074: v8(17.89,41.44) 17.48,41.03 v9(17.47,41.03)
  L11_GND w0.071: v8(17.89,41.44) 17.1,41.44 16.52,40.87 v6(16.52,40.62)
LOL_5N: length 19.3
  TOP w0.14: U1.AG7 17.02,25.66 17.65,25.66 17.84,25.47 v3(17.84,25.23)
  L3_GND w0.081: v8(19.37,39.86) 19.37,38.7 19.26,38.59 19.26,37.78 18.92,37.44 18.92,35.55 19.14,35.33 19.14,28.12 17.9,26.89 17.9,25.29 v3(17.84,25.23)
  L11_GND w0.071: v8(19.37,39.86) 18.44,39.86 17.7,40.59 17.45,40.59 v6(17.13,40.27)
LOL_6N: length 19.2
  TOP w0.076: 17.33,31.5 17.19,31.36 16.73,31.36 U1.AF18
  TOP w0.14: v4(16.62,35.9) 16.93,35.9 17.58,35.25 17.58,32.89 17.33,32.64 17.33,31.5
  L4_SIG1 w0.074: v9(19.22,41.17) 19.81,40.59 19.81,38.78 19.22,38.19 19.22,37.23 18.47,36.48 18.47,36.18 18.22,35.93 16.65,35.93 v4(16.62,35.9)
  L9_SIG2 w0.074: v9(19.22,41.17) 19.12,41.17 17.82,42.47 v7(17.58,42.47)
  L10_GND w0.081: v7(17.58,42.47) 17.58,42.46 17.13,42.46 16.44,41.78 16.44,41.36 16.12,41.03 16.12,40.77 15.92,40.57 v6(15.92,40.27)
LOL_7N: length 15.5
  TOP w0.14: v9(19.36,40.52) 19.36,39.73 17.92,38.29 17.92,32.77 17.61,32.47 17.61,31.4 17.33,31.11 U1.AG18
  L9_SIG2 w0.074: v7(17.5,42.02) 17.86,42.02 v9(19.36,40.52)
  L10_GND w0.081: v7(17.5,42.02) 16.95,42.02 16.63,41.7 16.63,41.28 16.32,40.97 16.32,40.55 v6(16.22,40.45)
LOL_8N: length 17.9
  L3_GND w0.081: v3(15.98,27.61) 15.98,27.09 16.32,26.75 16.85,26.75 17.03,26.93 17.03,27.69 18.41,29.06 18.41,33.24 18.04,33.61 18.04,35.31 18.27,35.54 18.27,36.87 v4(18.22,36.92)
  L4_SIG1 w0.074: v7(18.55,39.55) 18.69,39.41 18.69,39.05 18.82,38.92 18.82,37.52 v4(18.22,36.92)
  L10_GND w0.081: v6(16.52,39.57) 16.93,39.86 17.26,39.86 17.56,39.55 v7(18.55,39.55)
LPWN/PRSN: length 45.2
  L2_GND w0.071: v4(3.29,35.94) 3.54,35.69 3.54,34.54 3.32,34.31 3.32,31.07 2.35,30.1 2.35,28.58 1.79,28.02 1.79,24.35 1.41,23.97 1.41,22.64 v4(1.54,22.51)
  L4_SIG1 w0.074: v4(1.54,22.51) 1.33,22.51 1.26,22.43 1.26,21.97 1.36,21.87 1.36,20.3 1.14,20.08 1.14,16.56 2.43,15.27 2.43,12.91 2.14,12.62 2.14,10.11 3.87,8.38 3.87,6.99 6.35,4.51 8.98,4.51 9.33,4.16 v6(9.33,3.74) ; v4(3.29,35.94) 3.39,36.04 v8(3.66,36.04)
  L11_GND w0.071: v8(3.66,36.04) 3.66,36.04 3.66,36.04 4.53,36.91 4.74,36.91 5.72,37.89 5.81,37.89 v6(6.08,37.89)
  BOTTOM w0.14: v6(9.33,3.74) 9.33,3.74 9.33,2.47 J1.17 ; U24.3 6.49,38.3 v6(6.08,37.89) 6.06,37.87 R5.1
LRXN1: length 19.2
  L9_SIG2 w0.102: v6(17.57,49.95) 17.8,49.72 arc(17.86,49.63) 17.88,49.53 17.88,47.51 arc(17.51,45.94) 16.51,44.69 arc(16.01,44.26) 15.53,43.81 arc(15.08,43.33) 14.65,42.83 arc(14.16,41.95) 13.99,40.96 13.99,38.29 arc(14.07,37.52) 14.33,36.8 15.02,35.38 arc(15.4,34.38) 15.58,33.32 arc(15.59,33.24) 15.59,33.16 15.59,32.73 v9(15.48,32.61)
LRXN2: length 15.8
  L9_SIG2 w0.102: v9(13.98,32.61) 14.09,32.73 14.09,33.62 arc(13.96,34.66) 13.58,35.63 13.46,35.87 13.46,35.87 arc(13,37.07) 12.85,38.33 12.86,41.18 arc(13.47,43.29) 14.92,44.95 15.13,45.11 arc(15.52,45.56) 15.66,46.15 15.66,46.63 arc(15.63,46.73) 15.58,46.82 v6(15.35,47.05)
LRXN3: length 18
  L9_SIG2 w0.102: v6(13.12,49.95) 13.35,49.72 arc(13.41,49.63) 13.43,49.53 13.43,46.44 arc(13.13,45.14) 12.49,43.97 arc(11.93,42.94) 11.73,41.79 11.73,38.05 arc(11.79,37.32) 11.97,36.61 12.27,35.74 arc(12.51,34.77) 12.59,33.77 12.59,32.73 v9(12.48,32.61)
LRXN4: length 14.7
  L9_SIG2 w0.102: v9(10.98,32.61) 11.09,32.73 11.09,33.86 arc(11.01,35.12) 10.78,36.37 arc(10.78,36.38) 10.77,36.39 arc(10.65,37.06) 10.61,37.75 10.61,41.53 10.61,43.2 arc(10.68,43.86) 10.87,44.5 arc(11.12,45.23) 11.21,46.01 11.21,46.63 arc(11.18,46.73) 11.12,46.83 v6(10.9,47.05)
LRXN5: length 17.6
  L9_SIG2 w0.102: v9(9.48,32.61) 9.59,32.73 9.59,33.53 9.55,36.11 arc(9.5,36.88) 9.47,37.66 9.47,43.94 arc(9.41,44.47) 9.23,44.96 arc(9.04,45.48) 8.98,46.03 8.98,49.54 arc(8.96,49.63) 8.91,49.72 v6(8.67,49.95)
LRXN6: length 15.1
  L9_SIG2 w0.102: v6(6.45,47.05) 6.67,46.82 arc(6.73,46.73) 6.76,46.63 6.76,46.28 arc(6.83,45.84) 7.04,45.45 7.04,45.45 arc(7.57,44.78) 8.05,44.07 arc(8.26,43.62) 8.33,43.13 8.33,37.97 arc(8.31,37.01) 8.26,36.06 8.09,33.58 8.09,32.73 v9(7.98,32.61)
LRXN7: length 18.4
  L9_SIG2 w0.102: v6(4.22,49.95) 4.44,49.73 arc(4.51,49.63) 4.53,49.52 4.53,46.8 arc(4.74,45.74) 5.34,44.84 6.38,43.8 arc(6.96,42.94) 7.16,41.91 7.16,36.9 arc(7.15,36.63) 7.11,36.36 6.63,33.98 arc(6.6,33.77) 6.59,33.55 6.59,32.73 v9(6.48,32.61)
LRXN8: length 16.2
  L9_SIG2 w0.102: v9(4.98,32.61) 5.09,32.73 5.09,33.52 arc(5.22,34.96) 5.62,36.35 arc(5.92,37.35) 6.02,38.38 6.02,41.71 arc(5.89,42.33) 5.54,42.86 2.53,45.87 arc(2.36,46.12) 2.31,46.41 2.31,46.62 arc(2.28,46.73) 2.22,46.83 v6(2,47.05)
LRXP1: length 19.2
  L9_SIG2 w0.102: v9(15.98,32.61) 15.86,32.73 15.86,33.16 arc(15.86,33.25) 15.85,33.34 arc(15.65,34.5) 15.24,35.6 14.55,37.01 arc(14.33,37.63) 14.26,38.29 14.26,40.96 arc(14.41,41.86) 14.86,42.66 arc(15.28,43.15) 15.72,43.62 arc(16.19,44.06) 16.68,44.48 arc(17.75,45.83) 18.15,47.51 18.15,49.53 arc(18.17,49.63) 18.23,49.72 v6(18.46,49.95) 18.46,49.95
LRXP2: length 15.8
  L9_SIG2 w0.102: v6(16.23,47.05) 16,46.82 arc(15.95,46.73) 15.92,46.63 15.92,46.15 arc(15.76,45.44) 15.29,44.89 15.08,44.73 arc(13.71,43.17) 13.13,41.17 13.12,38.33 arc(13.26,37.13) 13.69,36 13.82,35.76 arc(14.22,34.73) 14.36,33.62 14.36,32.73 v9(14.48,32.61)
LRXP3: length 18
  L9_SIG2 w0.102: v6(14.01,49.95) 13.78,49.72 arc(13.72,49.63) 13.7,49.53 13.7,46.43 arc(13.39,45.05) 12.71,43.81 12.7,43.81 arc(12.18,42.86) 12,41.79 12,38.05 arc(12.06,37.36) 12.23,36.7 12.53,35.82 arc(12.78,34.81) 12.86,33.77 12.86,32.73 v9(12.98,32.61)
LRXP4: length 14.7
  L9_SIG2 w0.102: v6(11.78,47.05) 11.56,46.83 arc(11.5,46.73) 11.47,46.63 11.47,46.01 arc(11.38,45.17) 11.12,44.38 arc(10.94,43.8) 10.88,43.2 10.88,41.65 10.88,41.65 10.88,37.75 arc(10.92,37.1) 11.04,36.45 11.04,36.44 arc(11.28,35.16) 11.36,33.86 11.36,32.73 11.36,32.73 v9(11.48,32.61)
LRXP5: length 17.6
  L9_SIG2 w0.102: v9(9.98,32.61) 9.86,32.73 9.86,33.53 9.82,36.11 9.82,36.12 arc(9.77,36.9) 9.74,37.67 9.74,43.94 arc(9.67,44.53) 9.47,45.08 arc(9.31,45.54) 9.25,46.03 9.25,49.54 arc(9.27,49.63) 9.32,49.72 v6(9.56,49.95)
LRXP6: length 15.1
  L9_SIG2 w0.102: v9(8.48,32.61) 8.36,32.73 8.36,33.57 8.53,36.04 arc(8.58,37) 8.6,37.96 8.6,43.13 arc(8.51,43.7) 8.28,44.22 arc(7.78,44.93) 7.25,45.62 7.25,45.63 arc(7.08,45.93) 7.02,46.28 7.02,46.63 arc(7.05,46.73) 7.11,46.82 v6(7.33,47.05)
LRXP7: length 18.4
  L9_SIG2 w0.102: v6(5.11,49.95) 4.88,49.73 arc(4.82,49.63) 4.8,49.52 4.8,46.8 arc(4.99,45.84) 5.53,45.03 6.57,43.99 6.57,43.99 arc(7.2,43.04) 7.43,41.91 7.43,36.9 arc(7.41,36.6) 7.37,36.31 6.9,33.92 arc(6.87,33.74) 6.86,33.55 6.86,32.73 v9(6.98,32.61)
LRXP8: length 16.2
  L9_SIG2 w0.102: v9(5.48,32.61) 5.36,32.73 5.36,33.52 arc(5.49,34.91) 5.87,36.26 5.87,36.25 arc(6.18,37.3) 6.29,38.38 6.29,41.71 arc(6.14,42.43) 5.73,43.05 2.72,46.06 arc(2.61,46.22) 2.57,46.41 2.57,46.62 arc(2.6,46.73) 2.66,46.83 v6(2.88,47.05)
LTX_N1: length 9.2
  L2_GND w0.102: v1(17.76,41.94) arc(17.88,41.82) 17.93,41.66 17.93,40.53 arc(17.81,39.95) 17.48,39.46 16.35,38.33 arc(15.79,37.49) 15.59,36.5 15.59,33.89 arc(15.56,33.74) v1(15.48,33.61)
LTX_N2: length 9.7
  L2_GND w0.102: v1(13.98,33.61) arc(14.06,33.74) 14.09,33.89 14.09,37.06 arc(14.3,38.12) 14.9,39.01 15,39.12 arc(15.17,39.34) 15.32,39.57 arc(15.6,40.24) 15.7,40.97 15.7,42.52 arc(15.65,42.69) v1(15.53,42.81)
LTX_N3: length 8.5
  L2_GND w0.102: v1(12.48,33.61) arc(12.56,33.74) 12.59,33.89 12.59,36.36 arc(12.67,37.43) 12.91,38.47 13.27,39.65 arc(13.4,40.16) 13.48,40.68 13.48,41.66 arc(13.43,41.82) v1(13.31,41.94)
LTX_N4: length 9.3
  L2_GND w0.102: v1(10.98,33.61) arc(11.06,33.74) 11.09,33.89 11.09,39.43 arc(11.1,39.71) 11.12,40 11.23,41.43 arc(11.25,41.71) 11.25,42 11.25,42.52 arc(11.2,42.69) v1(11.08,42.81)
LTX_N5: length 8.6
  L2_GND w0.102: v1(9.48,33.61) arc(9.56,33.74) 9.59,33.89 9.59,37.76 arc(9.56,38.2) 9.47,38.63 9.15,39.68 9.16,39.66 arc(9.06,40.18) 9.02,40.71 9.02,41.66 arc(8.98,41.82) v1(8.86,41.94)
LTX_N6: length 9.6
  L2_GND w0.102: v1(7.98,33.61) arc(8.06,33.74) 8.09,33.89 8.09,37.9 arc(7.87,39.01) 7.24,39.95 arc(6.92,40.44) 6.8,41.01 6.8,42.52 arc(6.75,42.69) v1(6.63,42.81)
LTX_N7: length 9.1
  L2_GND w0.102: v1(6.48,33.61) arc(6.56,33.74) 6.59,33.89 6.59,37.81 arc(6.41,38.71) 5.9,39.47 4.99,40.38 arc(4.68,40.84) 4.58,41.39 4.58,41.66 arc(4.53,41.82) v1(4.41,41.94)
LTX_N8: length 10.3
  L2_GND w0.102: v1(2.18,42.81) arc(2.3,42.69) 2.35,42.52 2.35,41.66 arc(2.46,41.11) 2.77,40.65 4.03,39.39 4.69,38.73 arc(4.99,38.28) 5.09,37.75 5.09,33.89 arc(5.06,33.74) v1(4.98,33.61)
LTX_P1: length 9.2
  L2_GND w0.102: v1(15.98,33.61) arc(15.89,33.74) 15.86,33.89 15.86,36.5 arc(16.04,37.38) 16.54,38.14 17.67,39.27 arc(18.06,39.85) 18.19,40.53 18.19,41.64 arc(18.24,41.81) v1(18.37,41.94)
LTX_P2: length 9.7
  L2_GND w0.102: v1(16.14,42.81) arc(16.02,42.68) 15.97,42.51 15.97,40.97 arc(15.77,39.88) 15.2,38.94 15.1,38.83 15.09,38.82 arc(14.55,38.01) 14.36,37.06 14.36,33.89 arc(14.39,33.74) v1(14.48,33.61)
LTX_P3: length 8.5
  L2_GND w0.102: v1(13.92,41.94) arc(13.79,41.81) 13.74,41.64 13.74,40.67 arc(13.66,40.12) 13.53,39.57 13.16,38.39 arc(12.94,37.39) 12.86,36.36 12.86,33.89 arc(12.89,33.74) v1(12.98,33.61)
LTX_P4: length 9.3
  L2_GND w0.102: v1(11.69,42.81) arc(11.57,42.68) 11.52,42.51 11.52,42 arc(11.51,41.7) 11.5,41.41 11.5,41.42 11.39,39.99 arc(11.39,39.98) 11.38,39.98 arc(11.37,39.7) 11.36,39.43 11.36,33.89 arc(11.39,33.74) v1(11.48,33.61)
LTX_P5: length 8.6
  L2_GND w0.102: v1(9.46,41.94) arc(9.34,41.81) 9.29,41.64 9.29,40.71 arc(9.33,40.21) 9.42,39.72 9.74,38.67 9.72,38.7 arc(9.83,38.23) 9.86,37.76 9.86,33.89 arc(9.89,33.74) v1(9.98,33.61)
LTX_P6: length 9.6
  L2_GND w0.102: v1(8.48,33.61) arc(8.39,33.74) 8.36,33.89 8.36,37.9 arc(8.12,39.11) 7.43,40.14 arc(7.16,40.54) 7.07,41.01 7.07,42.51 arc(7.12,42.68) v1(7.24,42.81)
LTX_P7: length 9.1
  L2_GND w0.102: v1(6.98,33.61) arc(6.89,33.74) 6.86,33.89 6.86,37.81 arc(6.66,38.81) 6.09,39.66 5.18,40.57 arc(4.93,40.95) 4.84,41.39 4.84,41.64 arc(4.89,41.81) v1(5.01,41.94)
LTX_P8: length 10.3
  L2_GND w0.102: v1(2.79,42.81) arc(2.67,42.68) 2.62,42.51 2.62,41.66 arc(2.71,41.22) 2.96,40.84 4.22,39.58 4.88,38.92 arc(5.23,38.39) 5.36,37.75 5.36,33.89 arc(5.39,33.74) v1(5.48,33.61)
LTXN1: length 2.3
  TOP w0.127: J2.3 17.66,44.1 17.87,43.89 17.87,42.64 17.76,42.52
LTXN2: length 4.3
  TOP w0.127: 15.53,43.39 15.64,43.51 15.64,46.79 15.44,47 J6.3
LTXN3: length 2.3
  TOP w0.127: J10.3 13.21,44.1 13.42,43.89 13.42,42.64 13.31,42.52
LTXN4: length 4.3
  TOP w0.127: J14.3 10.98,47.01 11.19,46.8 11.19,43.51 11.08,43.39
LTXN5: length 2.3
  TOP w0.127: J3.3 8.76,44.1 8.97,43.89 8.97,42.64 8.86,42.52
LTXN6: length 4.3
  TOP w0.127: J7.3 6.53,47 6.74,46.79 6.74,43.51 6.63,43.39
LTXN7: length 2.3
  TOP w0.127: 4.41,42.52 4.52,42.64 4.52,43.89 4.31,44.1 J11.3
LTXN8: length 4.3
  TOP w0.127: 2.18,43.39 2.29,43.51 2.29,46.79 2.09,47 J15.3
LTXP1: length 2.3
  TOP w0.127: 18.37,42.52 18.25,42.64 18.25,43.89 18.46,44.1 J2.2
LTXP2: length 4.3
  TOP w0.127: 16.14,43.39 16.03,43.51 16.03,46.79 16.24,47 J6.2
LTXP3: length 2.3
  TOP w0.127: J10.2 14.01,44.1 13.8,43.89 13.8,42.64 13.92,42.52
LTXP4: length 4.3
  TOP w0.127: 11.69,43.39 11.58,43.51 11.58,46.79 11.79,47 J14.2
LTXP5: length 2.3
  TOP w0.127: 9.46,42.52 9.35,42.64 9.35,43.89 9.56,44.1 J3.2
LTXP6: length 4.3
  TOP w0.127: J7.2 7.34,47 7.13,46.79 7.13,43.51 7.24,43.39
LTXP7: length 2.3
  TOP w0.127: J11.2 5.11,44.1 4.9,43.89 4.9,42.64 5.01,42.52
LTXP8: length 4.3
  TOP w0.127: J15.2 2.89,47 2.68,46.79 2.68,43.51 2.79,43.39
M_INT: length 11.4
  L11_GND w0.071: v6(16.26,36.94) 16.08,36.76 11.16,36.76 v6(11.01,36.91)
  BOTTOM w0.14: U2.B4 15.61,37.95 16.26,37.3 v6(16.26,36.94) ; v6(11.01,36.91) 11.01,36.57 10.51,36.07 9.92,36.07 9.52,35.67 8.47,35.67 8.17,35.97 R31.2 8.17,36.31
M_LPWN: length 13.2
  L11_GND w0.071: v6(8.18,37.39) 9.17,36.4 v6(17.18,36.4)
  BOTTOM w0.14: v6(17.18,36.4) 17.18,37.14 16.22,38.1 U2.B6 ; v6(8.18,37.39) R29.2 8.07,37.39 7.57,36.9 U24.1
M_RSTN: length 15.5
  L4_SIG1 w0.074: v6(16.67,37.1) 17.2,36.57 18.3,36.57 19,37.27 19,38.4 v6(19.47,38.88)
  L11_GND w0.071: v6(10.47,36.9) 10.79,36.58 16.31,36.58 16.67,36.95 v6(16.67,37.1)
  BOTTOM w0.14: R28.2 10.71,37.14 v6(10.47,36.9) 10.46,36.9 U4.1 ; v6(19.47,38.88) 19.47,39.32 19.32,39.48 C60.2 19.31,39.64 R599.2 ; v6(16.67,37.1) 16.67,37.27 15.92,38.02 U2.A5
MCU33: length 12.2
  L9_SIG2 w0.254: v6(15.87,42.68) 15.87,42.36 v9(15.55,42.03)
  L11_GND w0.254: v6(17.53,42.74) 17.31,42.52 16.03,42.52 v6(15.87,42.68)
  BOTTOM w0.14: U2.T8 16.83,41.32 16.95,41.72 17.52,42.29 v6(17.52,42.74) C43.2 ; v6(17.64,37.32) 17.39,37.32 16.52,38.18 U2.A7 ; v6(15.87,42.68) 15.87,42.25 15.31,41.69 U2.R3
  BOTTOM w0.145: U2.B2 U2.A1
  BOTTOM w0.203: U2.R1 14.64,41.04 13.87,41.04 13.85,41.05 ; U2.H10 17.64,39.75 17.84,39.54 17.84,38.48 17.63,38.7 U2.B10
  BOTTOM w0.254: 14.21,41.05 13.85,41.05
  vias: v6(15.34,37.05) v6(15.64,37.05) v6(18.07,38.23) v7(15.34,37.05) v7(15.64,37.05) v7(18.07,38.23) v8(15.34,37.05) v8(15.64,37.05) v8(18.07,38.23) v9(15.34,37.05) v9(15.64,37.05) v9(18.07,38.23)
MCU_SPI_CLK: length 9.1
  TOP w0.14: R15.2 v2(1.93,38.66) 1.72,38.46 R41.1 U17.10
  L10_GND w0.081: v6(4.94,41.35) 4.67,41.08 4.67,39.86 4.37,39.56 3.21,39.56 2.3,38.66 v2(1.93,38.66)
  BOTTOM w0.14: U22.C1 6.11,41.57 5.95,41.73 5.32,41.73 v6(4.94,41.35)
MCU_SPI_CSB: length 11.9
  TOP w0.14: U17.8 v1(2.47,36.62)
  L2_GND w0.071: v1(2.47,36.62) 2.47,37.63 2.12,37.98 v2(1.28,37.98)
  L10_GND w0.081: v8(3.48,39.26) 3.17,39.26 1.88,37.98 v2(1.28,37.98)
  L11_GND w0.071: v6(7.66,40.4) 7.45,40.2 6.32,40.2 6.07,40.45 3.85,40.45 3.48,40.08 v8(3.48,39.26)
  BOTTOM w0.14: R10.2 1.11,37.8 v2(1.28,37.98) ; R40.1 7.8,40.26 v6(7.66,40.4) U22.A2
MCU_SPI_MISO: length 9.1
  TOP w0.14: v2(2.78,37.44) U17.7
  L11_GND w0.071: v2(2.78,37.44) 2.51,37.72 2.51,40.24 3.03,40.77 3.25,40.77 3.75,41.27 3.76,41.27 3.79,41.3 4.48,41.3 4.96,41.78 5.96,41.78 v6(6.81,40.93)
  BOTTOM w0.14: U22.B2 v6(6.81,40.93)
MCU_SPI_MOSI: length 6.2
  TOP w0.14: U17.9 v1(2.09,37.47)
  BOTTOM w0.14: U22.D1 4.53,40.47 4.53,40.03 4.05,39.55 R12.2 3.47,39.55 2.09,38.17 v1(2.09,37.47)
MISO_SLV: length 18.7
  TOP w0.14: U46.5 2.47,33.93 2.58,33.93 3.34,34.68 3.34,36.91 v4(3.21,37.04)
  L4_SIG1 w0.074: v7(15.73,37.85) 14.92,38.66 6.81,38.66 5.18,37.04 v4(3.21,37.04)
  L10_GND w0.081: v7(15.73,37.85) 16.04,38.16 16.04,39.1 v6(15.92,39.22)
MISO_SLV_18: length 31.1
  L2_GND w0.071: v4(18.79,34.26) 18.54,34.26 17.64,33.35 17.64,31.6 18.17,31.07 18.17,30.51 18.95,29.74 18.95,28.82 v1(18.86,28.73)
  L4_SIG1 w0.074: v4(1.78,29.02) 1.74,29.06 1.74,32.16 1.18,32.72 1.18,33.74 1.34,33.9 v4(1.48,33.9) 1.48,35.03 1.87,35.42 2.33,35.42 2.64,35.1 16.3,35.1 17.15,34.26 v4(18.79,34.26)
MODE_SEL0: length 30.2
  TOP w0.14: R404.1 2.87,28.47 v3(3.09,28.47) 3.09,28.48 R769.2
  L3_GND w0.081: v3(4.98,28.11) 4.69,27.82 3.74,27.82 v3(3.09,28.47) 2.87,28.69 2.87,29.97 3.46,30.56 3.46,34 4.16,34.71 4.16,36.97 4.06,37.07 4.06,37.78 v4(4.3,38.01)
  L4_SIG1 w0.074: v4(4.3,38.01) v7(4.3,40.05)
  L10_GND w0.081: v7(4.3,40.05) 4.3,41.56 v8(4.29,41.58)
  L11_GND w0.071: v8(4.29,41.58) 4.4,41.58 4.82,41.99 7.06,41.99 7.6,42.54 7.88,42.54 8.42,42 13.7,42 14.45,41.25 15.63,41.25 15.92,40.97 v6(15.92,40.62)
MOSI_SLV: length 21.3
  TOP w0.14: U46.4 2.17,33.56 2.66,33.56 3.64,34.54 3.64,37.21 3.4,37.44 v4(3.21,37.44)
  L4_SIG1 w0.074: v4(3.21,37.44) 3.42,37.24 4.91,37.24 6.69,39.02 15.76,39.02 16.4,38.38 v7(16.4,37.95)
  L10_GND w0.081: v7(16.4,37.95) 16.22,38.12 16.22,39.39 v6(16.22,39.4)
MOSI_SLV_18: length 5.9
  L3_GND w0.081: v4(3.44,30.02) 3.95,30.02 4.48,29.5 v3(4.48,29.11)
  L4_SIG1 w0.074: v4(3.44,30.02) 3.17,30.29 3.17,30.78 2.73,31.22 2.73,32.59 v4(1.74,33.58)
Net_8:
  vias: v3(14.95,29.98) v3(16.09,26.57)
NRST: length 2.6
  L10_GND w0.081: v6(16.83,39.4) 17,39.27 18.16,39.27 v6(18.31,39.12)
  BOTTOM w0.14: R603.2 18.33,39.1 v6(18.31,39.12) ; R599.1 C455.2
OSFP_SCL: length 53.6
  L7_PWR2 w0.076: v6(11.28,3.39) 11.47,3.39 13.33,5.25 15.23,5.25 17.99,8.01 17.99,11.91 v10(18.13,12.04) ; v8(15.55,40.9) 15.99,40.46 15.99,38.91 16.42,38.48 16.91,38.48 17.23,38.16 17.23,36.69 v6(17.64,36.29)
  L8_GND w0.076: v6(17.64,36.29) 18.01,35.92 18.01,33.36 18.9,32.47 18.9,29.97 18.23,29.31 18.23,12.95 18.13,12.84 v10(18.13,12.04)
  L9_SIG2 w0.074: v8(15.98,41.55) 15.99,41.53 15.99,41.34 v8(15.55,40.9)
  L11_GND w0.071: v6(9.47,42.89) 9.82,43.23 10.45,43.23 11.08,42.6 13.87,42.6 14.44,42.03 15.22,42.03 15.54,41.71 15.82,41.71 v8(15.98,41.55) ; v8(15.55,40.9) v6(15.61,40.8)
  BOTTOM w0.14: v6(11.28,3.39) 11.1,3.2 J1.14 ; U48.1 9,42.81 TP1.1
OSFP_SDA: length 57.7
  TOP w0.254: J1.47 v9(11.4,3.8)
  L7_PWR2 w0.076: v8(15.15,41.7) 15.15,40.79 15.76,40.19 v8(15.76,38.34) 15.76,38.34 15.82,38.28 16.78,38.28 17,38.05 17,35.91 17.64,35.27 v6(17.64,35.25) ; v9(11.4,3.8) 11.41,3.79 11.62,3.79 13.26,5.43 15.13,5.43 17.8,8.1 17.8,12.13 v10(18.42,12.74)
  L8_GND w0.076: v8(19.32,35.27) 18.68,35.27 18.22,34.82 18.22,33.43 19.13,32.52 19.13,29.91 18.42,29.2 v10(18.42,12.74)
  L11_GND w0.071: v8(19.32,35.27) 17.66,35.27 v6(17.64,35.25) ; v6(15.92,38.87) 15.92,38.5 v8(15.76,38.34) ; v8(15.15,41.7) 14.5,41.7 13.82,42.38 11.05,42.38 10.37,43.06 10.12,43.06 9.66,42.6 9.29,42.6 9.2,42.68 9.2,43.53 v6(9.47,43.8)
  BOTTOM w0.14: U48.3 9.48,44.21 TP2.1
PHY_I2C_LS_EN: length 15.6
  L11_GND w0.071: v6(13.92,39.77) 11.4,39.77 10.45,40.73 9.53,40.73 8.35,39.55 5.71,39.55 5.54,39.38 4.54,39.38 v6(3.91,40.01)
  BOTTOM w0.14: v6(3.91,40.01) 3.72,40.21 R73.1 3.72,42.45 3.44,42.73 U10.8 ; U2.J1 14.07,39.92 v6(13.92,39.77)
PHY_I2C_SCL_33: length 16.3
  L4_SIG1 w0.074: v11(16.62,39.25) 16.12,39.75 6.29,39.75 5.41,40.64 3.56,40.64 3.35,40.43 v6(3.12,40.43)
  BOTTOM w0.14: v6(3.12,40.43) 3.14,40.42 R579.2 3.29,40.43 3.29,42.02 3.05,42.25 U10.1
  vias: v6(16.52,39.22) v7(16.52,39.22) v8(16.52,39.22)
PHY_I2C_SDA_33: length 17.7
  L4_SIG1 w0.074: v11(16.62,38.79) 16.41,39.01 16.41,39.01 16.03,39.38 6.25,39.38 5.26,40.37 3.65,40.37 3.39,40.11 2.69,40.11 v6(2.03,40.77)
  BOTTOM w0.14: U10.3 2.05,40.79 v6(2.03,40.77) 2.02,40.76 R580.2
  vias: v6(16.52,38.87) v7(16.52,38.87) v8(16.52,38.87)
PHY_INTR_N_18: length 25.6
  L3_GND w0.081: v8(0.94,40.99) 0.94,40.62 0.8,40.48 0.8,37.78 1.94,36.65 1.94,35.61 1.65,35.32 1.65,34.94 1.89,34.7 1.89,34.2 2.13,33.96 2.13,32.7 1.27,31.84 1.27,26.92 3.02,25.18 4.91,25.18 v3(4.98,25.11)
  L11_GND w0.071: v8(0.94,40.99) 1.43,40.99 1.69,41.25 1.69,41.46 2.28,42.05 2.64,42.05 3.23,42.64 v6(4.58,42.64)
  BOTTOM w0.14: v6(4.58,42.64) R583.2 4.8,43.03 4.8,43.03 U38.7
PHY_INTR_N_33: length 11.6
  L11_GND w0.071: v6(15.06,38.29) 14.88,38.29 14.05,39.12 10.97,39.12 10.02,40.07 v6(9.87,40.07)
  BOTTOM w0.14: U38.5 6.66,42.43 7.41,41.68 9.17,41.68 9.87,40.98 v6(9.87,40.07) ; v6(15.06,38.29) 15.07,38.29 U2.A3
PHY_RST_N_0_18: length 28
  L3_GND w0.081: v3(4.48,27.11) 4.48,26.83 4.24,26.59 3.34,26.59 2.88,27.05 2.12,27.05 1.93,27.24 1.93,28.01 2.3,28.37 2.3,30.35 2.88,30.93 2.88,34.3 3.57,34.99 3.57,36.6 3.51,36.66 3.51,38.45 2.74,39.22 2.15,39.22 1.53,39.84 v4(1.53,40.14)
  L4_SIG1 w0.074: v8(1.3,43.73) 1.07,43.73 0.43,43.09 0.43,40.82 0.85,40.4 1.28,40.4 v4(1.53,40.14)
  L11_GND w0.071: v6(4.75,44.35) 1.92,44.35 v8(1.3,43.73)
  BOTTOM w0.14: R856.2 4.58,44.19 v6(4.75,44.35) 5.11,44.35 5.37,44.09 U38.10
PHY_RST_N_0_33: length 13.2
  L11_GND w0.071: v6(7.26,44.18) 7.73,44.66 10.52,44.66 11.91,43.27 14.87,43.27 16,42.14 v6(16.76,42.14)
  BOTTOM w0.14: U38.2 6.37,44.09 7.16,44.09 v6(7.26,44.18) ; v6(16.76,42.14) 16.67,42.14 15.92,41.38 U2.R5
PHY_RST_N_1_18: length 36.7
  TOP w0.076: 17.26,25.36 16.73,25.36 U1.AF7
  TOP w0.14: 17.26,25.36 17.35,25.36 v3(17.46,25.25)
  L3_GND w0.081: v3(17.46,25.25) 17.69,25.48 17.69,26.27 17.49,26.47 17.49,27.63 18.77,28.91 18.77,33.39 18.41,33.76 18.41,35.03 18.73,35.35 18.73,37.57 19.07,37.91 19.07,39.12 v4(19.09,39.13)
  L4_SIG1 w0.074: v8(18.03,43.07) 18.18,43.07 18.75,42.5 18.92,42.5 19.23,42.19 19.23,41.73 18.87,41.37 18.87,39.72 19.06,39.53 19.06,39.16 v4(19.09,39.13)
  L11_GND w0.071: v8(18.03,43.07) 17.4,43.07 17.16,42.83 17.15,42.83 17.14,42.82 16.16,42.82 15.54,43.44 15.43,43.44 15.43,43.44 15.23,43.44 11.98,43.44 10.58,44.83 7.66,44.83 7.34,44.51 5.49,44.51 4.99,44.01 v6(4.99,44)
  BOTTOM w0.14: R855.2 4.58,43.59 v6(4.99,44) 4.99,43.97 5.24,43.72 U38.9
PHY_RST_N_1_33: length 11.3
  L11_GND w0.071: v6(7.76,42.23) 8.17,41.82 13.61,41.82 14.36,41.08 15.12,41.08 15.28,40.92 15.28,40.72 15.55,40.45 v6(15.61,40.45)
  BOTTOM w0.14: v6(7.76,42.23) R582.1 7.74,43.72 U38.3
PHY_SELF_INIT_18: length 55.9
  L2_GND w0.071: v1(18.83,28.24) 18.83,28.25 ; 18.83,28.25 18.83,28.25 ; 18.83,28.25 18.55,28.53 18.55,28.83 18.76,29.04 18.76,29.59 17.88,30.47 17.88,30.85 v4(17.53,31.2)
  L3_GND w0.081: v4(4.48,26.11) 2.4,26.11 1.45,27.06 1.45,31.69 2.32,32.56 2.32,34.02 2.07,34.27 2.07,34.77 1.83,35.01 1.83,35.25 2.12,35.54 2.12,36.72 0.99,37.86 0.99,40.41 1.23,40.64 1.23,41.18 v8(1,41.4)
  L4_SIG1 w0.074: v4(17.53,31.2) 17.85,31.52 17.85,33.08 16.19,34.74 3.8,34.74 3.6,34.54 3.6,31.85 3.81,31.64 4.62,31.64 4.99,31.27 4.99,30.38 5.46,29.91 5.46,29.61 5.82,29.25 5.82,27.89 4.48,26.54 v4(4.48,26.11)
  L11_GND w0.071: v6(5.92,43.33) 5.51,42.92 4.2,42.92 4.12,42.84 3.14,42.84 2.53,42.22 2.15,42.22 1.34,41.4 v8(1,41.4)
